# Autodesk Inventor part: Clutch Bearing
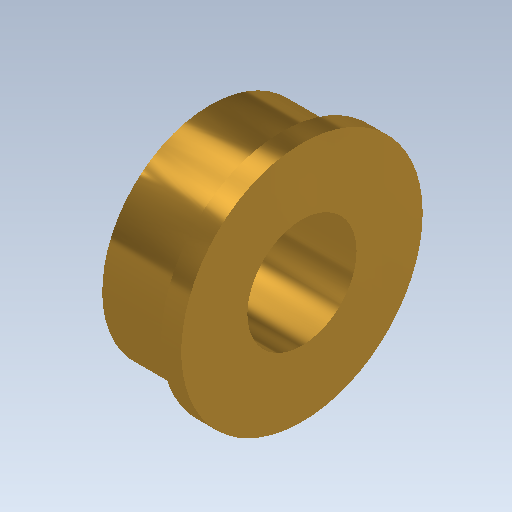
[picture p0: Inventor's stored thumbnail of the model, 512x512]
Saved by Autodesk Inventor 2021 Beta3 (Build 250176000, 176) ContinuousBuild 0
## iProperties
Created: 2012-08
Part Number: Clutch Bearing
Material: Brass, Soft Yellow
Document SubType Name: Modeling
Designer: John
Mass: 1.20107 g
Surface Area: 2.76966 cm^2
Volume: 0.141803 cm^3
Density: 8.47 g/cm^3
Appearance: Brass - Satin
Author: John
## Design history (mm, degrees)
sketch "Sketch1"
  geometry: C1 r 4.763 at (0, 0); 1 further point
  constraints: 1 centre point, 1 coincident
  dimensions: "d0" = 9.525 diameter of C1
extrude "Extrusion1" new body sketch "Sketch1" distance "d1" = 3.175; taper "d2" = 0 deg
sketch "Sketch2"
  geometry: C1 r 4.763 at (0, 0) reference; C2 r 5.334 at (0, 0)
  constraints: 1 centre point, 1 coincident
  dimensions: "d4" = 10.668 diameter of C2
extrude "Extrusion2" join sketch "Sketch2" distance "d6" = 0.889; taper "d7" = 0 deg
sketch "Sketch3"
  geometry: C1 r 5.334 at (0, 0) reference
hole "Hole1" sketch "Sketch3" at (0, 0) diameter "d8" = 4.826; stored, may be unused: countersink angle "d12" = 82 deg, drill point angle "d14" = 118 deg; dims "d9" = 19.05, "d10" = 9.525, "d11" = 6.35, "d13" = 25.4
body "Solid1"
